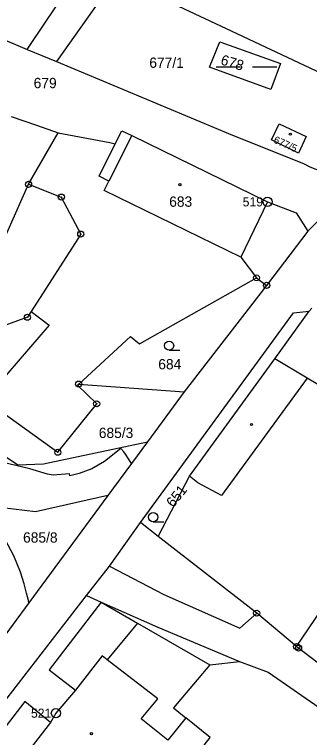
# Model space of a CAD drawing. Extents: x -749778 to -749372, y -967291 to -966955.
# Drawn here: x -749556.3 to -749507.7, y -967221.1 to -967101.9 of the extents above; entities that cross this region are included whole.
import ezdxf

# ---------------------------------------------------------------- set-up
doc = ezdxf.new("R2010")
doc.units = 0
for name, color, linetype in [('Hranice parcel', 7, 'Continuous'), ('Parcelní čísla', 7, 'Continuous'), ('Vnitřní kresba', 7, 'Continuous'), ('Značky bodu BP', 7, 'Continuous'), ('Značky budov', 7, 'Continuous'), ('Značky kultur', 7, 'Continuous')]:
    doc.layers.add(name, color=color, linetype=linetype)

msp = doc.modelspace()

# ---------------------------------------------------------------- linework, layer by layer
at = {"layer": 'Hranice parcel'}
for p, q in [((-749576.24, -967098.5), (-749554.23, -967107.67)), ((-749554.23, -967107.67), (-749549.42, -967109.68)), ((-749554, -967129.9), (-749549.11, -967121.42)), ((-749516.41, -967145.31), (-749514.74, -967146.55)), ((-749514.74, -967146.55), (-749528.34, -967164.11)), ((-749507.71, -967150.81), (-749507.3, -967150.29)), ((-749545.74, -967162.82), (-749528.34, -967164.11)), ((-749528.34, -967164.11), (-749534.4, -967172.34)), ((-749534.4, -967172.34), (-749537.02, -967175.91)), ((-749537.02, -967175.91), (-749540.92, -967181.19)), ((-749540.92, -967181.19), (-749553.95, -967198.86)), ((-749532.62, -967187.94), (-749535.56, -967185.6)), ((-749553.95, -967198.86), (-749569.6, -967220.07))]:
    msp.add_line(p, q, dxfattribs=at)
for points in [[(-749536.81, -967092.95), (-749537.33, -967092.65), (-749549.42, -967109.68)], [(-749536.81, -967092.95), (-749538.87, -967096), (-749521.44, -967104.24), (-749491.04, -967118.52)], [(-749554.23, -967107.67), (-749553.8, -967107.04), (-749549.38, -967100.48)], [(-749522.44, -967106.43), (-749512.48, -967109.98), (-749514.07, -967114.3), (-749524.19, -967110.59), (-749522.44, -967106.43)], [(-749549.42, -967109.68), (-749521.02, -967121.52), (-749508.54, -967126.52)], [(-749556.87, -967118.72), (-749552.69, -967120.13), (-749549.11, -967121.42)], [(-749509.51, -967124.77), (-749513.96, -967122.57), (-749512.69, -967119.91), (-749508.23, -967122.03), (-749509.51, -967124.77)], [(-749549.11, -967121.42), (-749540.6, -967123.03), (-749539.71, -967123.25), (-749538.6, -967121.09), (-749536.99, -967121.88), (-749514.59, -967132.79), (-749518.97, -967141.9), (-749516.41, -967145.31)], [(-749495.53, -967125.22), (-749507.92, -967137.64), (-749514.74, -967146.55)], [(-749508.54, -967126.52), (-749507.61, -967127.01), (-749506.64, -967127.41), (-749505.63, -967127.72), (-749504.6, -967127.93), (-749503.56, -967128.04), (-749502.51, -967128.05), (-749502.18, -967128.03), (-749501.14, -967127.91), (-749500.11, -967127.69), (-749499.11, -967127.38), (-749498.14, -967126.97), (-749497.22, -967126.47), (-749496.34, -967125.89), (-749495.53, -967125.22)], [(-749575.24, -967161.82), (-749562.35, -967148.01), (-749561.39, -967146.09), (-749559.94, -967143.18), (-749554, -967129.9)], [(-749554, -967129.9), (-749548.6, -967132), (-749545.4, -967138.1), (-749553.6, -967150.87), (-749554.2, -967151.8), (-749560.25, -967154), (-749563.2, -967151.9), (-749568.8, -967159.2), (-749561.22, -967165.4), (-749549.18, -967174.04), (-749542.77, -967166.07), (-749545.93, -967163), (-749545.74, -967162.82)], [(-749545.74, -967162.82), (-749537.19, -967154.99), (-749535.71, -967156.16), (-749516.41, -967145.31)], [(-749535.56, -967185.6), (-749510.32, -967151.05), (-749507.71, -967150.81)], [(-749532.62, -967187.94), (-749527.44, -967178), (-749513.39, -967158.64), (-749507.71, -967150.81)], [(-749509.79, -967206.06), (-749488, -967173.92), (-749482.75, -967163.3)], [(-749580.28, -967171.75), (-749574.93, -967170.19), (-749566.54, -967170.41), (-749561.52, -967172.29), (-749555.8, -967176.14), (-749551.55, -967175.94), (-749534.4, -967172.34)], [(-749537.02, -967175.91), (-749538.03, -967174.36), (-749538.28, -967173.97), (-749538.76, -967173.43), (-749541.48, -967175.55), (-749543.56, -967176.77), (-749545.65, -967177.56), (-749547.19, -967177.95), (-749547.26, -967177.59), (-749549.92, -967177.81), (-749550.89, -967177.68), (-749553.79, -967176.8), (-749558.39, -967175.68), (-749560.79, -967175.03), (-749562.93, -967175.31), (-749563.04, -967175.46), (-749563.04, -967175.6), (-749568.49, -967173.77), (-749571.33, -967173.01), (-749574.23, -967172.55), (-749581.95, -967172.24)], [(-749540.92, -967181.19), (-749552.88, -967183.89), (-749558.28, -967183.21), (-749565.92, -967178.54), (-749568.07, -967177.26), (-749572.83, -967177.39)], [(-749553.95, -967198.86), (-749554.04, -967198.48), (-749554.32, -967197.29), (-749554.75, -967195.73), (-749555.32, -967193.83), (-749556.46, -967191.11), (-749557.79, -967188.52), (-749558.73, -967187.21), (-749559.52, -967186.11), (-749560.17, -967185.38), (-749561.59, -967184.04), (-749562.48, -967183.46), (-749563.86, -967182.82), (-749568.6, -967181.36), (-749570.54, -967180.87), (-749571.89, -967180.6)], [(-749544.44, -967197.63), (-749540.67, -967192.84), (-749535.56, -967185.6)], [(-749509.79, -967206.06), (-749516.38, -967200.56), (-749532.62, -967187.94)], [(-749576.96, -967239.3), (-749574.4, -967236.29), (-749544.44, -967197.63)], [(-749544.44, -967197.63), (-749542.05, -967198.77), (-749532.66, -967202.89), (-749519.24, -967208.54), (-749514.5, -967210.26), (-749496.94, -967222.41)], [(-749493.61, -967217.22), (-749506.47, -967208.63), (-749509.47, -967206.32), (-749509.79, -967206.06)], [(-749547.13, -967251.19), (-749539.73, -967241.65), (-749548.27, -967234.85), (-749542.52, -967227.63), (-749538.01, -967231.22), (-749539.89, -967233.59), (-749535.96, -967236.61), (-749531.53, -967230.62), (-749532.42, -967229.96), (-749530.45, -967227.43), (-749529.58, -967228.12), (-749524.04, -967221.02), (-749528.05, -967217.79), (-749531.02, -967221.51), (-749535.46, -967217.96), (-749532.69, -967214.65), (-749541.02, -967208.23), (-749541.86, -967207.58), (-749546.28, -967213.26), (-749549.5, -967217.04), (-749550.38, -967218.55), (-749560.87, -967232.04), (-749564.94, -967237.28)]]:
    msp.add_lwpolyline(points, dxfattribs=at)
at = {"layer": 'Vnitřní kresba'}
for p, q in [((-749536.99, -967121.88), (-749540.75, -967129.37)), ((-749542.36, -967128.56), (-749539.71, -967123.25)), ((-749540.75, -967129.37), (-749542.36, -967128.56)), ((-749541.52, -967130.91), (-749540.75, -967129.37)), ((-749518.97, -967141.9), (-749541.52, -967130.91)), ((-749514.59, -967132.79), (-749509.86, -967134.6)), ((-749509.86, -967134.6), (-749507.92, -967137.64)), ((-749553.6, -967150.87), (-749550.63, -967153.13)), ((-749550.63, -967153.13), (-749561.22, -967165.4)), ((-749508.05, -967161.85), (-749513.39, -967158.64)), ((-749508.05, -967161.85), (-749522.2, -967181.2)), ((-749488, -967173.92), (-749508.05, -967161.85)), ((-749526.07, -967179.07), (-749527.44, -967178)), ((-749522.2, -967181.2), (-749526.07, -967179.07)), ((-749540.67, -967192.84), (-749531.72, -967197.46)), ((-749531.72, -967197.46), (-749519.14, -967203.02)), ((-749542.05, -967198.77), (-749550.61, -967209.92)), ((-749542.05, -967198.77), (-749536.05, -967202.21)), ((-749519.14, -967203.02), (-749516.38, -967200.56)), ((-749536.05, -967202.21), (-749541.02, -967208.23)), ((-749536.05, -967202.21), (-749524.09, -967209.08)), ((-749524.09, -967209.08), (-749519.24, -967208.54)), ((-749550.61, -967209.92), (-749546.28, -967213.26)), ((-749524.09, -967209.08), (-749530.1, -967216.14)), ((-749554.64, -967215.12), (-749572.33, -967238.1)), ((-749550.38, -967218.55), (-749554.64, -967215.12)), ((-749530.1, -967216.14), (-749528.05, -967217.79))]:
    msp.add_line(p, q, dxfattribs=at)
at = {"layer": 'Značky bodu BP'}
for centre, radius in [((-749554, -967129.9), 0.5), ((-749554, -967129.9), 0.0303), ((-749548.6, -967132), 0.5), ((-749548.6, -967132), 0.0303), ((-749514.59, -967132.79), 0.75), ((-749514.59, -967132.79), 0.03), ((-749545.4, -967138.1), 0.5), ((-749545.4, -967138.1), 0.0303), ((-749516.41, -967145.31), 0.5), ((-749516.41, -967145.31), 0.0303), ((-749514.74, -967146.55), 0.5), ((-749514.74, -967146.55), 0.0303), ((-749554.2, -967151.8), 0.5), ((-749554.2, -967151.8), 0.0303), ((-749545.74, -967162.82), 0.5), ((-749545.74, -967162.82), 0.0303), ((-749542.77, -967166.07), 0.5), ((-749542.77, -967166.07), 0.0303), ((-749549.18, -967174.04), 0.5), ((-749549.18, -967174.04), 0.0303), ((-749516.38, -967200.56), 0.5), ((-749516.38, -967200.56), 0.0303), ((-749509.79, -967206.06), 0.5), ((-749509.47, -967206.32), 0.5), ((-749509.79, -967206.06), 0.0303), ((-749509.47, -967206.32), 0.0303), ((-749549.5, -967217.04), 0.75), ((-749549.5, -967217.04), 0.03)]:
    msp.add_circle(centre, radius, dxfattribs=at)
at = {"layer": 'Značky budov'}
for centre in [(-749510.83, -967121.63), (-749529.04, -967129.96), (-749517.25, -967169.48), (-749543.64, -967220.42)]:
    msp.add_circle(centre, 0.175, dxfattribs=at)
at = {"layer": 'Značky kultur'}
for p, q in [((-749523.09, -967110.57), (-749519.07, -967110.57)), ((-749517.06, -967110.57), (-749513.04, -967110.57)), ((-749530.82, -967157.23), (-749529.07, -967157.23)), ((-749533.45, -967185.49), (-749531.7, -967185.49))]:
    msp.add_line(p, q, dxfattribs=at)
for centre in [(-749530.82, -967156.48), (-749533.45, -967184.74)]:
    msp.add_circle(centre, 0.75, dxfattribs=at)

# ---------------------------------------------------------------- texts
at = {"layer": 'Parcelní čísla'}
for s, height, rotation, p in [('678', 1.7, 343, (-749522.45, -967110.11)), ('677/5', 1.2, 336, (-749513.71, -967123)), ('651', 1.7, 51, (-749530.14, -967183.26))]:
    msp.add_text(s, height=height, rotation=rotation, dxfattribs=at).set_placement(p)
for s, p in [('677/1', (-749534.09, -967110.71)), ('679', (-749553.16, -967114.06)), ('683', (-749530.81, -967133.6)), ('684', (-749532.61, -967160.39)), ('685/3', (-749542.42, -967171.7)), ('685/8', (-749554.91, -967188.94))]:
    msp.add_text(s, height=1.7, dxfattribs=at).set_placement(p)
at = {"layer": 'Značky bodu BP'}
for s, p in [('519', (-749518.69, -967133.54)), ('521', (-749553.6, -967217.79))]:
    msp.add_text(s, height=1.5, dxfattribs=at).set_placement(p)

doc.saveas('drawing.dxf')
